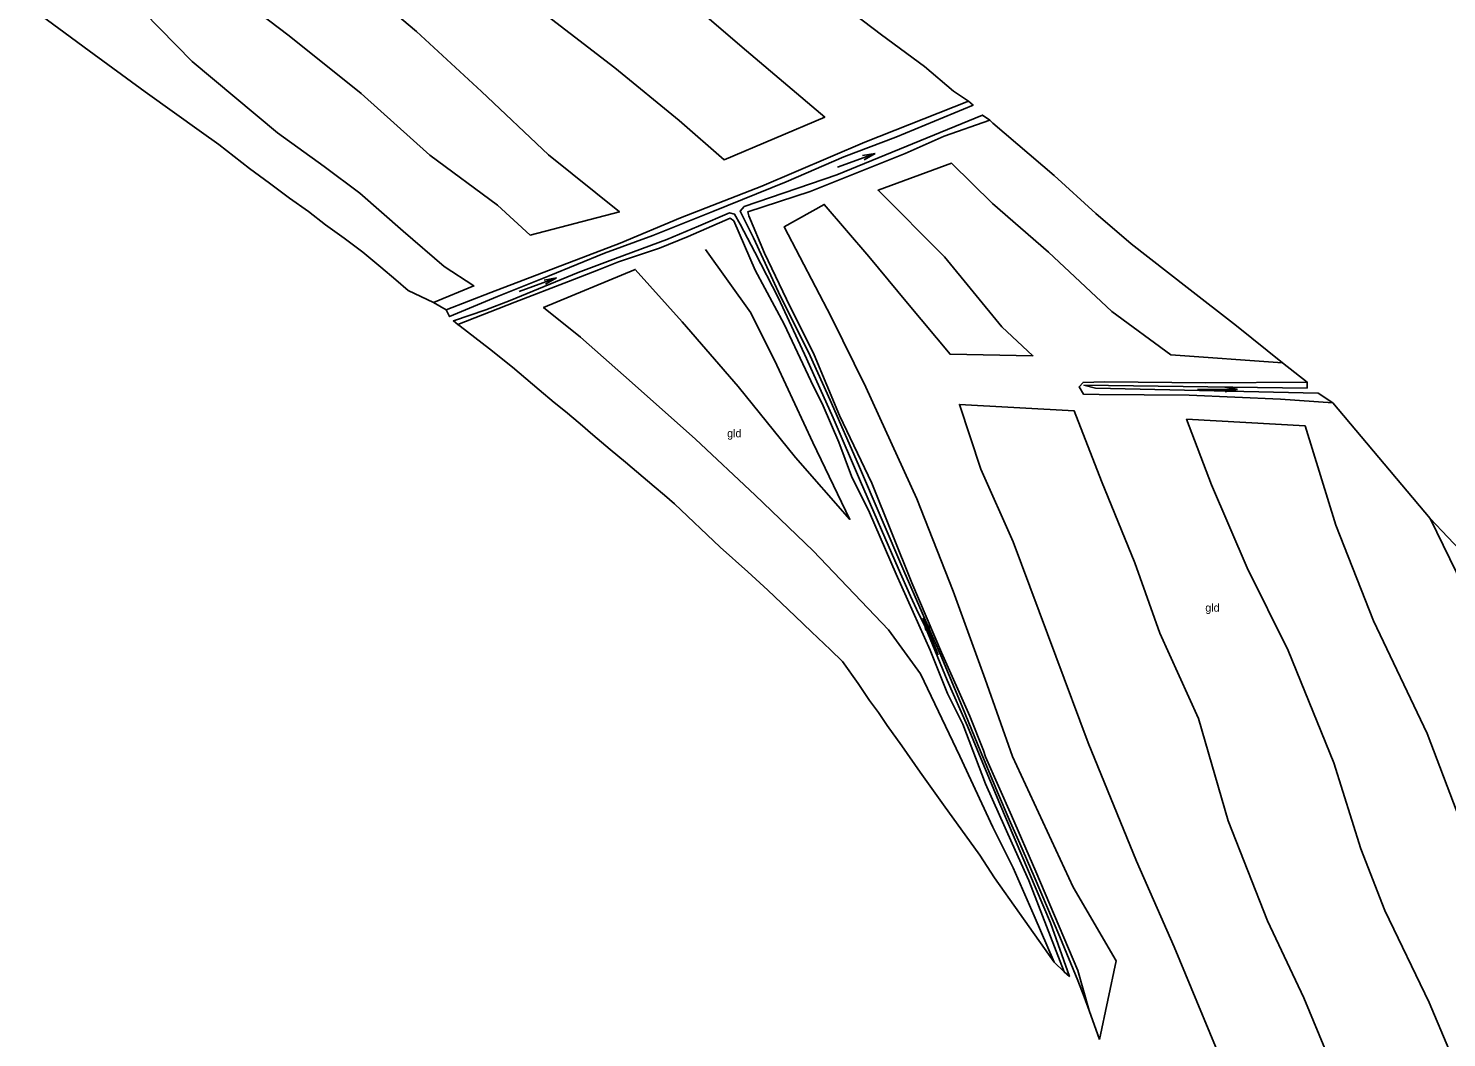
# Model space of a CAD drawing. Extents: x 154825 to 158680, y 370717 to 378075.
# Drawn here: x 156725.8 to 156903, y 374775 to 374901.2 of the extents above; entities that cross this region are included whole.
import ezdxf

# ---------------------------------------------------------------- set-up
doc = ezdxf.new("R2010")
doc.units = 0
for name, color, linetype in [('grasland_productiegrasl(vs)', 7, 'Continuous'), ('hoogteverschillijn', 7, 'Continuous'), ('insteek sloot', 7, 'Continuous'), ('Sloot bodem', 7, 'Continuous'), ('stroomrichting  watergangen', 7, 'Continuous'), ('vlak_Grasland', 7, 'Continuous'), ('vlak_Grazige_vegetatie', 7, 'Continuous')]:
    doc.layers.add(name, color=color, linetype=linetype)

msp = doc.modelspace()

# ---------------------------------------------------------------- linework, layer by layer
at = {"layer": 'hoogteverschillijn'}
for points in [[(156749.25, 374907.25), (156758.36, 374900.27), (156767.38, 374893.08), (156775.93, 374885.38), (156784.39, 374879.1), (156788.49, 374875.38), (156799.63, 374878.27), (156790.79, 374885.42), (156782.4, 374893.33), (156774.27, 374900.85), (156767.19, 374906.85)], [(156823.06, 374907.53), (156832.39, 374900.42), (156837.77, 374896.46), (156841.39, 374893.39)], [(156725.77, 374903.99), (156733.35, 374898.41), (156740.36, 374893.3), (156747.39, 374888.26), (156749.57, 374886.69), (156753.39, 374883.71), (156755.92, 374881.85), (156758.39, 374879.99), (156760.76, 374878.33), (156762.91, 374876.66), (156765.25, 374875), (156767.56, 374873.23), (156769.8, 374871.35), (156771.68, 374869.8), (156773.24, 374868.45), (156776.41, 374866.93), (156781.45, 374869.01), (156777.72, 374871.46), (156772.6, 374875.85), (156767.21, 374880.61), (156762.75, 374883.95), (156756.92, 374888.17), (156746.25, 374897.1), (156738.18, 374905.39)], [(156787.89, 374904.91), (156799.08, 374896.27), (156807.12, 374889.69), (156812.71, 374884.77), (156825.29, 374890.12), (156815.53, 374898.42), (156805.97, 374906.61)], [(156846.29, 374889.37), (156853.98, 374882.83), (156859.18, 374878.07), (156863.6, 374874.28), (156870.59, 374868.84), (156876.76, 374864.04), (156882.51, 374859.4), (156868.57, 374860.42), (156861.17, 374865.82), (156853.28, 374873.23), (156846.26, 374879.32), (156841.12, 374884.35), (156831.97, 374880.98), (156840.28, 374872.64), (156847.42, 374863.9), (156851.32, 374860.29), (156840.96, 374860.47), (156835.64, 374866.85), (156830.81, 374872.68), (156825.23, 374879.2), (156820.22, 374876.39), (156826.11, 374865.16), (156830.44, 374856.36), (156836.79, 374842.4), (156841.35, 374830.84), (156845.33, 374819.84), (156848.78, 374810.16), (156856.34, 374793.83), (156861.71, 374784.61), (156859.64, 374774.79)], [(156779.75, 374863.97), (156783.39, 374861.16), (156786.28, 374858.85), (156789.62, 374856.01), (156791.49, 374854.45), (156792.9, 374853.33), (156794.72, 374851.76), (156796.31, 374850.41), (156798.47, 374848.55), (156800.41, 374846.97), (156803.97, 374843.95), (156805.27, 374842.85), (156806.52, 374841.77), (156812.21, 374836.34), (156815.7, 374833.28), (156818.18, 374830.97), (156821.62, 374827.74), (156823.66, 374825.76), (156826.03, 374823.51), (156827.52, 374822.05), (156829.46, 374819.3), (156830.91, 374817.2), (156832.01, 374815.67), (156833.09, 374814.07), (156834.93, 374811.52), (156837.22, 374808.2), (156840.12, 374804.14), (156844.66, 374797.84), (156846.52, 374795.02), (156849.63, 374790.57), (156853.98, 374784.48), (156851.45, 374790.24), (156848.84, 374796.27), (156846.29, 374801.33), (156842.16, 374810.23), (156837.28, 374820.52), (156833.27, 374826), (156823.84, 374835.91), (156816.61, 374842.87), (156809.13, 374849.85), (156801.21, 374856.88), (156794.76, 374862.62), (156790.17, 374866.3), (156801.62, 374871.08), (156807.47, 374864.52), (156814.49, 374856.45), (156821.64, 374847.58), (156828.45, 374839.83), (156823.83, 374849.44), (156819.29, 374859.13), (156816.08, 374865.66), (156810.39, 374873.59)], [(156876.25, 374768.8), (156868.98, 374786.36), (156864.27, 374797.09), (156858.21, 374811.88), (156854.17, 374822.72), (156848.86, 374837.03), (156844.81, 374846.11), (156842.13, 374854.21), (156856.49, 374853.38), (156859.87, 374844.6), (156864.06, 374834.4), (156867.17, 374825.62), (156872.01, 374814.92), (156875.73, 374802.13), (156880.62, 374789.63), (156885.16, 374779.99), (156889.73, 374769.04)], [(156906.89, 374765.1), (156900.83, 374779.42), (156895.29, 374790.91), (156892.3, 374798.62), (156888.93, 374809.37), (156883.22, 374823.42), (156878.09, 374833.76), (156873.64, 374844.16), (156870.51, 374852.35), (156885.33, 374851.51), (156889.19, 374839.09), (156893.87, 374827.16), (156900.6, 374813.06), (156904.67, 374802.28)], [(156905.88, 374829.85), (156900.95, 374839.95), (156911.99, 374828.26)]]:
    msp.add_lwpolyline(points, dxfattribs=at)
at = {"layer": 'insteek sloot'}
for points in [[(156843.26, 374892.11), (156830.29, 374887), (156817.43, 374881.5), (156807.28, 374877.53), (156799.72, 374874.37), (156783.55, 374868.21), (156777.99, 374866.03)], [(156858.33, 374778.4), (156856.93, 374783.43), (156851.68, 374795.78), (156848.64, 374802.81), (156845.39, 374810.12), (156845.14, 374810.91), (156843.41, 374815.24), (156839.91, 374823.18), (156836.17, 374831.89), (156831.18, 374844.35), (156827.16, 374852.81), (156823.98, 374860.41), (156820.53, 374867.38), (156817.75, 374873.1), (156815.8, 374877.77), (156815.68, 374878.27), (156823.48, 374880.81), (156835.33, 374885.58), (156840.23, 374887.74), (156845.91, 374889.74)], [(156779.44, 374864.2), (156786.58, 374866.97), (156793.26, 374869.58), (156797.04, 374871.03), (156799.52, 374872.02), (156804.63, 374873.73), (156808.23, 374875.18), (156813.49, 374877.49), (156813.93, 374877.16), (156816.6, 374870.99), (156820.21, 374864.25), (156823.58, 374857.14), (156825.09, 374854.02), (156827.06, 374849.5), (156828.66, 374845.21), (156830.89, 374840.67), (156834.24, 374832.96), (156838.47, 374823.46), (156840.63, 374818.04), (156842.56, 374814.2), (156845.4, 374806.75), (156848.73, 374799.3), (156850.81, 374794.67), (156855.23, 374783.27)], [(156888.79, 374854.39), (156882.26, 374854.85), (156870.84, 374855.34), (156859.59, 374855.45), (156857.64, 374855.48), (156857.09, 374856.39), (156857.58, 374856.95), (156860.25, 374857.03), (156872.9, 374856.88), (156885.6, 374856.97)]]:
    msp.add_lwpolyline(points, dxfattribs=at)
at = {"layer": 'Sloot bodem'}
for points in [[(156778.41, 374865.18), (156784.42, 374867.71), (156790.85, 374870.29), (156797.77, 374873.1), (156803.82, 374875.32), (156811.3, 374878.34), (156820.46, 374882.05), (156827.67, 374885.14), (156834.19, 374887.62), (156843.84, 374891.62)], [(156845, 374890.39), (156826.79, 374882.89), (156815.23, 374878.96), (156814.71, 374878.35), (156816.41, 374875.03), (156819.52, 374868.22), (156823.46, 374860.26), (156825.99, 374854.72), (156829.5, 374846.64), (156835.2, 374833.39), (156837.47, 374828.16), (156839.79, 374822.79), (156842.48, 374816.43), (156844.42, 374811.62), (156846.89, 374805.7), (156848.36, 374802.31), (156849.7, 374799.31), (156851.46, 374795.17), (156854.67, 374787.62), (156856.91, 374782.18), (156857.7, 374780.11)], [(156855.87, 374782.69), (156853.5, 374789.37), (156849.91, 374797.78), (156847.19, 374804.26), (156845.05, 374809.34), (156843.14, 374813.99), (156840.58, 374819.73), (156837.88, 374826.32), (156836.76, 374828.6), (156836.01, 374830.21), (156834.48, 374833.72), (156829.76, 374844.55), (156826.37, 374852.54), (156823.02, 374859.93), (156819.51, 374867.47), (156816.58, 374873.25), (156814.71, 374876.72), (156814.02, 374877.99), (156813.4, 374878.15), (156809.5, 374876.5), (156805.58, 374874.82), (156799.14, 374872.45), (156794.5, 374870.7), (156785.98, 374867.18), (156782.95, 374866.03), (156778.9, 374864.65)], [(156886.96, 374855.61), (156859.15, 374856.24), (156857.69, 374856.59), (156885.57, 374856.24)]]:
    msp.add_lwpolyline(points, dxfattribs=at)
at = {"layer": 'stroomrichting  watergangen'}
for p, q in [((156826.91, 374883.87), (156831.61, 374885.58)), ((156831.59, 374885.59), (156830.03, 374885.31)), ((156831.61, 374885.58), (156830.24, 374884.79)), ((156787.1, 374868.31), (156791.79, 374870.02)), ((156791.77, 374870.02), (156790.22, 374869.75)), ((156791.79, 374870.02), (156790.42, 374869.23)), ((156871.89, 374856.05), (156876.88, 374856.08)), ((156876.86, 374856.09), (156875.31, 374856.36)), ((156876.88, 374856.08), (156875.33, 374855.79)), ((156837.58, 374827.49), (156837.92, 374825.95)), ((156839.49, 374822.89), (156837.59, 374827.51)), ((156837.59, 374827.51), (156838.44, 374826.18))]:
    msp.add_line(p, q, dxfattribs=at)
at = {"layer": 'vlak_Grasland'}
for points in [[(156823.06, 374907.53), (156832.39, 374900.42), (156837.77, 374896.46), (156841.39, 374893.39), (156843.26, 374892.11), (156830.29, 374887), (156817.43, 374881.5), (156807.28, 374877.53), (156799.72, 374874.37), (156783.55, 374868.21), (156777.99, 374866.03), (156776.41, 374866.93), (156773.24, 374868.45), (156771.68, 374869.8), (156769.8, 374871.35), (156767.56, 374873.23), (156765.25, 374875), (156762.91, 374876.66), (156760.76, 374878.33), (156758.39, 374879.99), (156755.92, 374881.85), (156753.39, 374883.71), (156749.57, 374886.69), (156747.39, 374888.26), (156740.36, 374893.3), (156733.35, 374898.41), (156725.77, 374903.99)], [(156859.64, 374774.79), (156858.33, 374778.4), (156856.93, 374783.43), (156851.68, 374795.78), (156848.64, 374802.81), (156845.39, 374810.12), (156845.14, 374810.91), (156843.41, 374815.24), (156839.91, 374823.18), (156836.17, 374831.89), (156831.18, 374844.35), (156827.16, 374852.81), (156823.98, 374860.41), (156820.53, 374867.38), (156817.75, 374873.1), (156815.8, 374877.77), (156815.68, 374878.27), (156823.48, 374880.81), (156835.33, 374885.58), (156840.23, 374887.74), (156845.91, 374889.74), (156846.29, 374889.37), (156853.98, 374882.83), (156859.18, 374878.07), (156863.6, 374874.28), (156870.59, 374868.84), (156876.76, 374864.04), (156882.51, 374859.4), (156885.6, 374856.97), (156872.9, 374856.88), (156860.25, 374857.03), (156857.58, 374856.95), (156857.09, 374856.39), (156857.64, 374855.48), (156859.59, 374855.45), (156870.84, 374855.34), (156882.26, 374854.85), (156888.79, 374854.39), (156900.95, 374839.95), (156911.99, 374828.26)]]:
    msp.add_lwpolyline(points, dxfattribs=at)
msp.add_lwpolyline([(156850.81, 374794.67), (156855.23, 374783.27), (156853.98, 374784.48), (156849.63, 374790.57), (156846.52, 374795.02), (156844.66, 374797.84), (156840.12, 374804.14), (156837.22, 374808.2), (156834.93, 374811.52), (156833.09, 374814.07), (156832.01, 374815.67), (156830.91, 374817.2), (156829.46, 374819.3), (156827.52, 374822.05), (156826.03, 374823.51), (156823.66, 374825.76), (156821.62, 374827.74), (156818.18, 374830.97), (156815.7, 374833.28), (156812.21, 374836.34), (156806.52, 374841.77), (156805.27, 374842.85), (156803.97, 374843.95), (156800.41, 374846.97), (156798.47, 374848.55), (156796.31, 374850.41), (156794.72, 374851.76), (156792.9, 374853.33), (156791.49, 374854.45), (156789.62, 374856.01), (156786.28, 374858.85), (156783.39, 374861.16), (156779.75, 374863.97), (156779.44, 374864.2), (156786.58, 374866.97), (156793.26, 374869.58), (156797.04, 374871.03), (156799.52, 374872.02), (156804.63, 374873.73), (156808.23, 374875.18), (156813.49, 374877.49), (156813.93, 374877.16), (156816.6, 374870.99), (156820.21, 374864.25), (156823.58, 374857.14), (156825.09, 374854.02), (156827.06, 374849.5), (156828.66, 374845.21), (156830.89, 374840.67), (156834.24, 374832.96), (156838.47, 374823.46), (156840.63, 374818.04), (156842.56, 374814.2), (156845.4, 374806.75), (156848.73, 374799.3)], close=True, dxfattribs=at)
at = {"layer": 'vlak_Grazige_vegetatie'}
for points in [[(156784.42, 374867.71), (156778.41, 374865.18), (156777.99, 374866.03), (156783.55, 374868.21), (156799.72, 374874.37), (156807.28, 374877.53), (156817.43, 374881.5), (156830.29, 374887), (156843.26, 374892.11), (156843.84, 374891.62), (156834.19, 374887.62), (156827.67, 374885.14), (156820.46, 374882.05), (156811.3, 374878.34), (156803.82, 374875.32), (156797.77, 374873.1), (156790.85, 374870.29)], [(156856.93, 374783.43), (156858.33, 374778.4), (156857.7, 374780.11), (156856.91, 374782.18), (156854.67, 374787.62), (156851.46, 374795.17), (156849.7, 374799.31), (156848.36, 374802.31), (156846.89, 374805.7), (156844.42, 374811.62), (156842.48, 374816.43), (156839.79, 374822.79), (156837.47, 374828.16), (156835.2, 374833.39), (156829.5, 374846.64), (156825.99, 374854.72), (156823.46, 374860.26), (156819.52, 374868.22), (156816.41, 374875.03), (156814.71, 374878.35), (156815.23, 374878.96), (156826.79, 374882.89), (156845, 374890.39), (156845.91, 374889.74), (156840.23, 374887.74), (156835.33, 374885.58), (156823.48, 374880.81), (156815.68, 374878.27), (156815.8, 374877.77), (156817.75, 374873.1), (156820.53, 374867.38), (156823.98, 374860.41), (156827.16, 374852.81), (156831.18, 374844.35), (156836.17, 374831.89), (156839.91, 374823.18), (156843.41, 374815.24), (156845.14, 374810.91), (156845.39, 374810.12), (156848.64, 374802.81), (156851.68, 374795.78)], [(156814.02, 374877.99), (156814.71, 374876.72), (156816.58, 374873.25), (156819.51, 374867.47), (156823.02, 374859.93), (156826.37, 374852.54), (156829.76, 374844.55), (156834.48, 374833.72), (156836.01, 374830.21), (156836.76, 374828.6), (156837.88, 374826.32), (156840.58, 374819.73), (156843.14, 374813.99), (156845.05, 374809.34), (156847.19, 374804.26), (156849.91, 374797.78), (156853.5, 374789.37), (156855.87, 374782.69), (156855.23, 374783.27), (156850.81, 374794.67), (156848.73, 374799.3), (156845.4, 374806.75), (156842.56, 374814.2), (156840.63, 374818.04), (156838.47, 374823.46), (156834.24, 374832.96), (156830.89, 374840.67), (156828.66, 374845.21), (156827.06, 374849.5), (156825.09, 374854.02), (156823.58, 374857.14), (156820.21, 374864.25), (156816.6, 374870.99), (156813.93, 374877.16), (156813.49, 374877.49), (156808.23, 374875.18), (156804.63, 374873.73), (156799.52, 374872.02), (156797.04, 374871.03), (156793.26, 374869.58), (156786.58, 374866.97), (156779.44, 374864.2), (156778.9, 374864.65), (156782.95, 374866.03), (156785.98, 374867.18), (156794.5, 374870.7), (156799.14, 374872.45), (156805.58, 374874.82), (156809.5, 374876.5), (156813.4, 374878.15)], [(156860.25, 374857.03), (156872.9, 374856.88), (156885.6, 374856.97), (156885.57, 374856.24), (156857.69, 374856.59), (156859.15, 374856.24), (156886.96, 374855.61), (156888.79, 374854.39), (156882.26, 374854.85), (156870.84, 374855.34), (156859.59, 374855.45), (156857.64, 374855.48), (156857.09, 374856.39), (156857.58, 374856.95)]]:
    msp.add_lwpolyline(points, close=True, dxfattribs=at)

# ---------------------------------------------------------------- texts
at = {"layer": 'grasland_productiegrasl(vs)'}
for p in [(156813.1, 374850.09), (156872.86, 374828.29)]:
    msp.add_text('gld', height=1, dxfattribs=at).set_placement(p)

doc.saveas('drawing.dxf')
